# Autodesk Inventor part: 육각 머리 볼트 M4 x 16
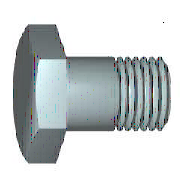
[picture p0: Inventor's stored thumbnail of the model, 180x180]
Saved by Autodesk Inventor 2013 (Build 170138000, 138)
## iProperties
IsCustomPart: 0
Created: 2012-02
Part Number: 육각 머리 볼트 M4 x 16
Material: 강철, 연강
Description: 6각 머리 볼트 및 6각 머리 나사
Document SubType Name: Modeling
Standard: KS B 1002
Designer: mduedu
Standards Organization: KS
Language: ko-KR
Size Designation: A + B M4 x 16
Categories: <MemberInstance><Categories><Category DisplayName="조임쇠" InternalName="e4da775c-781d-43d5-af7c-5136215cf5a6" Mnemonic="FSTN"><Category DisplayName="볼트" InternalN
Density: 7.86 g/cm^3
Mass: 2.45486 g
Surface Area: 3.4613 cm^2
Volume: 0.312323 cm^3
Author: mduedu
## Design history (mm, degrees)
sketch "스케치1"
  geometry: L1 (0, 2.94)-(0, 2); L2 (2.1, 2)-(16, 2); L3 (16, 2)-(16, 0); L4 (16, 0)-(-0.4, 0); L5 (-3.68, 0)-(19.28, 0) reference; L6 (-0.4, 0)-(-0.4, 2.94); L7 (-0.4, 2.94)-(0, 2.94); L8 (2.1, 2)-(1.67, 2); L9 (1.67, 2)-(0, 2); L10 (0, -0.588)-(0, 3.528) reference
  constraints: 16 end point, 2 collinear, 2 perpendicular, 1 parallel
  dimensions: "d0" = 16 distance between parallel lines of L3 L1 (= NLG); "d1" = 13.9 distance from line of L2.start L3 (= GEL); "d2" = 4 diameter of L2 L4 (= GD); "d9" = 0.4001 distance between parallel lines of L6 L1 (computed from SD); "d10" = 5.88 diameter of L7 L4 (= SD2); "d13" = 0.42952 distance of L2.start L8.end (computed from GAL); "d14" = 4 diameter of L9 L4 (= BDM)
revolve "본체" sketch "스케치1" stored, may be unused: angle "d12" = 90 deg
sketch "스케치2"
  geometry: L1 (0, 4.041)-(3.5, 2.021); L2 (3.5, 2.021)-(3.5, -2.021); L3 (3.5, -2.021)-(0, -4.041); L4 (0, -4.041)-(-3.5, -2.021); L5 (-3.5, -2.021)-(-3.5, 2.021); L6 (-3.5, 2.021)-(0, 4.041); 2 further points
  constraints: 12 end point, 1 coincident, 1 vertical, 11 other
  dimensions: "d11" = 7 distance between parallel lines of L5 L2 (= SW)
extrude "머리" join sketch "스케치2" distance "d3" = 2.4 (= KOH - SD); taper "d4" = 0 deg
sketch "스케치4"
  geometry: L1 (-2.8, 3.5)-(-2.8, 4.041); L2 (-2.8, 4.041)-(-2.487, 4.041); L3 (-2.487, 4.041)-(-2.8, 3.5); L4 (-3.28, 0)-(0.08, 0) reference; L5 (-0.4, 4.041)-(-2.8, 4.041) reference; L6 (-2.8, 2.021)-(-2.8, 4.041) reference
  constraints: 6 end point, 2 collinear, 1 perpendicular, 1 vertical
  dimensions: "d5" = 30 deg angle of L3 L1 (= ANG1); "d19" = 7 diameter of L1.start L4 (= SW0)
revolve "모따기1" sketch "스케치4" stored, may be unused: angle "d21" = 90 deg
workplane "Work Plane1"
body "Solid1"
feature "스레드" dims "d15" = 13.9 (= GEL), "d16" = 0
chamfer "모따기2" distance "d6" = 0.42941 (= -0.5 x SPD + 0.5 x GD); stored, may be unused: second distance "d7" = 0.42952 (computed from GUL), angle "d55" = 45 deg
other parameters: "NLG" = 16 [user parameter; used in 1 equation term], "GD" = 4 (= NND) [user parameter; used in 2 equation terms], "BDM" = 4 (= NND) [user parameter; used in 1 equation term], "KOH" = 2.8 [user parameter; used in 1 equation term], "GEL" = 13.9 [user parameter; used in 2 equation terms], "SW" = 7 [user parameter; used in 3 equation terms], "SW0" = 7 (= SW) [user parameter; used in 1 equation term], "SPD" = 3.14117 (= NND - 1.2269 x PTC) [user parameter; used in 1 equation term], "SD2" = 5.88 (= SDH) [user parameter; used in 1 equation term], "SD" = 0.4 [user parameter; used in 2 equation terms], "ANG1" = 30 deg [user parameter; used in 1 equation term], "GAL" = 0.42941 (= 0.61345 x PTC) [user parameter; used in 1 equation term], "GUL" = 0.42941 (= 0.61345 x PTC) [user parameter; used in 1 equation term], "d8" = 0, "RR" = 0.2 [user parameter], "d57" = 0, "d58" = 0, "TPU" = 14.28571 (computed from PTC) [user parameter], "GD1" = 3.14117 (= THREADDIA - 1.2269 x PTC) [user parameter], "THREADDIA" = 4 [user parameter; used in 1 equation term], "SDH" = 5.88 [user parameter; used in 1 equation term], "SDHG" = 2.1 [user parameter], "TOA" = 30 deg [user parameter], "PTC" = 0.7 [user parameter; used in 5 equation terms], "NND" = 4 [user parameter; used in 3 equation terms], "E0" = 8.085 (= 1.155 x SW) [user parameter]
